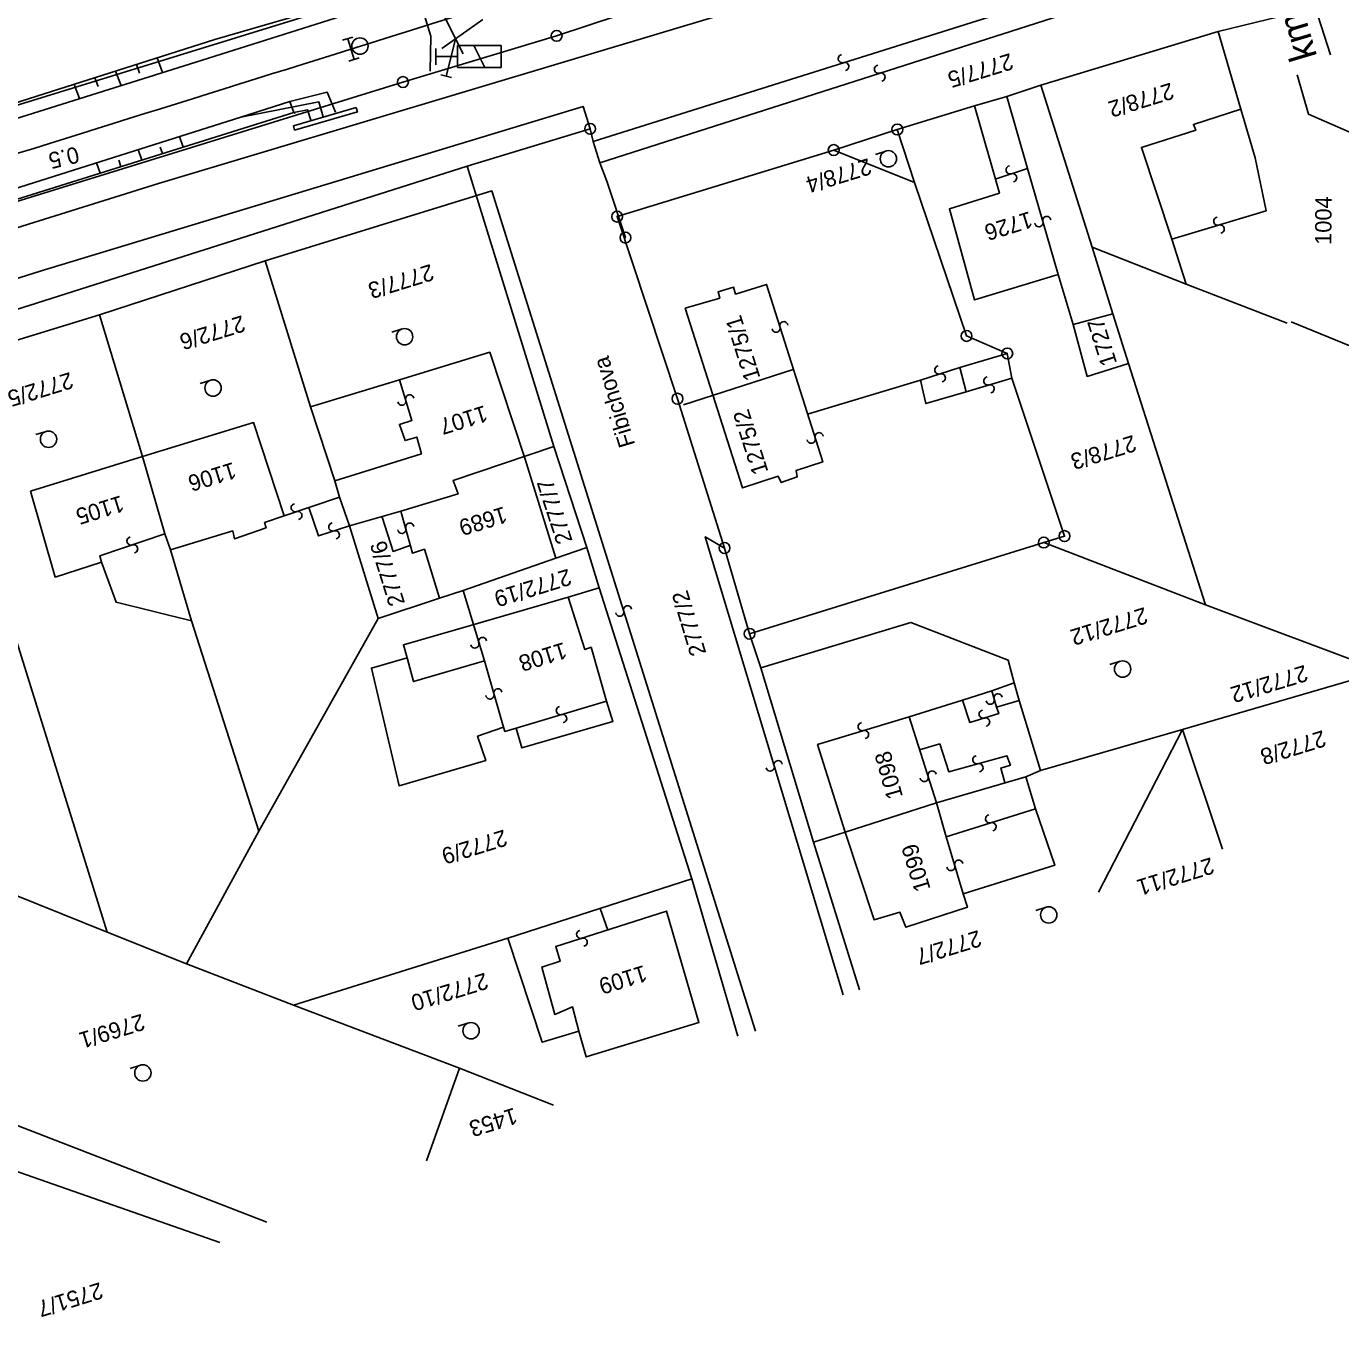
# Model space of a CAD drawing. Extents: x -658910 to -658078, y -1170373 to -1169331.
# Drawn here: x -658648.2 to -658527.6, y -1170123.2 to -1170003.8 of the extents above; entities that cross this region are included whole.
import ezdxf

# ---------------------------------------------------------------- set-up
doc = ezdxf.new("R2010")
doc.units = 0
for name, color, linetype in [('Vrstva 1', 7, 'Continuous'), ('Vrstva 10', 7, 'Continuous'), ('Vrstva 11', 7, 'Continuous'), ('Vrstva 13', 7, 'Continuous'), ('Vrstva 20', 7, 'Continuous'), ('Vrstva 23', 7, 'Continuous'), ('Vrstva 30', 7, 'Continuous'), ('Vrstva 6', 7, 'Continuous'), ('Vrstva 8', 7, 'Continuous'), ('Vrstva 9', 7, 'Continuous')]:
    doc.layers.add(name, color=color, linetype=linetype)

msp = doc.modelspace()

# ---------------------------------------------------------------- linework, layer by layer
at = {"layer": 'Vrstva 1'}
for p, q in [((-658599.613, -1170004.705), (-658599.513, -1170004.705)), ((-658613.714, -1170008.939), (-658613.614, -1170008.939))]:
    msp.add_line(p, q, dxfattribs=at)
for points in [[(-658750.043, -1170042.514), (-658671.512, -1170017.973), (-658613.207, -1169999.979)], [(-658585.293, -1169999.957), (-658599.563, -1170004.705), (-658613.664, -1170008.939), (-658714.84, -1170040.211), (-658749.914, -1170050.912)]]:
    msp.add_lwpolyline(points, dxfattribs=at)
for centre in [(-658599.563, -1170004.705), (-658613.664, -1170008.939)]:
    msp.add_circle(centre, 0.499, dxfattribs=at)
at = {"layer": 'Vrstva 10'}
for p, q in [((-658636.22, -1170006.729), (-658635.715, -1170008.066)), ((-658640.032, -1170007.941), (-658639.533, -1170009.262)), ((-658638.126, -1170007.335), (-658637.827, -1170008.128)), ((-658643.844, -1170009.153), (-658643.351, -1170010.459)), ((-658641.938, -1170008.547), (-658641.639, -1170009.339)), ((-658621.753, -1170010.1), (-658621.753, -1170010.1)), ((-658633.815, -1170014.909), (-658634.156, -1170013.926)), ((-658637.632, -1170016.104), (-658637.97, -1170015.132)), ((-658635.723, -1170015.506), (-658635.926, -1170014.923)), ((-658641.449, -1170017.299), (-658641.783, -1170016.338)), ((-658639.541, -1170016.702), (-658639.743, -1170016.118))]:
    msp.add_line(p, q, dxfattribs=at)
for points in [[(-658858.81, -1170075.77), (-658835.33, -1170068.814), (-658806.5, -1170059.46), (-658781.728, -1170051.951), (-658759.08, -1170044.56), (-658716.43, -1170031.76), (-658690.72, -1170023.742), (-658663.72, -1170015.47), (-658630.927, -1170005.047), (-658619.527, -1170001.735), (-658614.09, -1169999.864), (-658613.911, -1169996.427), (-658615.839, -1169976.036), (-658616.28, -1169953.162), (-658614.25, -1169933.651)], [(-658610.105, -1169934.508), (-658612.959, -1169952.166), (-658613.171, -1169975.75), (-658611.485, -1169997.195), (-658611.739, -1169999.997), (-658613.983, -1170001.632), (-658619.297, -1170002.886), (-658632.661, -1170007.108), (-658660.45, -1170015.82), (-658687.716, -1170024.188), (-658719.16, -1170034.07), (-658752.32, -1170044.29), (-658781.421, -1170053.208), (-658807.34, -1170061.38), (-658834.998, -1170069.996)], [(-658619.86, -1170011.71), (-658620.63, -1170009.86), (-658624.05, -1170010.73), (-658623.66, -1170011.73)], [(-658623.66, -1170011.73), (-658624.05, -1170010.73), (-658620.63, -1170009.86), (-658619.86, -1170011.71)], [(-658623.66, -1170011.73), (-658661.96, -1170023.72), (-658756.86, -1170053.2), (-658808.03, -1170068.81), (-658856.9, -1170084.05), (-658891.09, -1170098.33)], [(-658628.54, -1170012.15), (-658624.05, -1170010.73)], [(-658628.54, -1170012.15), (-658621.38, -1170010.76), (-658620.97, -1170012.14)], [(-658623.66, -1170011.73), (-658622.409, -1170011.477), (-658622.11, -1170012.44)], [(-658623.66, -1170011.73), (-658622.409, -1170011.477), (-658622.11, -1170012.44)], [(-658623.615, -1170011.792), (-658623.56, -1170011.788)], [(-658714.67, -1170038.92), (-658662.28, -1170022.82), (-658628.54, -1170012.15)]]:
    msp.add_lwpolyline(points, dxfattribs=at)
at = {"layer": 'Vrstva 13'}
msp.add_lwpolyline([(-658611.169, -1170007.954), (-658611.101, -1170004.744), (-658611.699, -1170002.836), (-658609.401, -1170001.323), (-658608.825, -1169993.398)], dxfattribs=at)
at = {"layer": 'Vrstva 20'}
for p, q in [((-658610.65, -1170005.85), (-658610.65, -1170007.35)), ((-658607.15, -1170005.6), (-658606.15, -1170007.6))]:
    msp.add_line(p, q, dxfattribs=at)
msp.add_lwpolyline([(-658610.65, -1170006.6), (-658608.65, -1170006.6), (-658608.65, -1170007.6), (-658604.65, -1170007.6), (-658604.65, -1170005.6), (-658608.65, -1170005.6), (-658608.65, -1170006.6)], dxfattribs=at)
at = {"layer": 'Vrstva 23'}
msp.add_line((-658535.91, -1169983.41), (-658528.549, -1170006.455), dxfattribs=at)
at = {"layer": 'Vrstva 30'}
for p, q in [((-658610.209, -1170002.229), (-658608.149, -1170006.353)), ((-658610.089, -1170005.867), (-658606.329, -1170003.201)), ((-658609.69, -1170008.39), (-658608.84, -1170004.995)), ((-658610.175, -1170008.269), (-658609.205, -1170008.511))]:
    msp.add_line(p, q, dxfattribs=at)
at = {"layer": 'Vrstva 6'}
for p, q in [((-658619.21, -1170005.11), (-658618.254, -1170004.818)), ((-658618.732, -1170004.964), (-658618.148, -1170006.876)), ((-658618.626, -1170007.022), (-658617.67, -1170006.73))]:
    msp.add_line(p, q, dxfattribs=at)
msp.add_lwpolyline([(-658617.95, -1170011.29), (-658617.839, -1170011.674), (-658623.6, -1170013.35), (-658623.713, -1170012.962)], close=True, dxfattribs=at)
msp.add_circle((-658617.611, -1170005.638), 0.75, dxfattribs=at)
for centre, radius, start, end in [((-655551.219, -1179788.762), 10252.407, 107.0611194, 107.4078056), ((-665545.791, -1147911.264), 23155.173, 287.1664083, 287.4078056)]:
    msp.add_arc(centre, radius, start, end, dxfattribs=at)
at = {"layer": 'Vrstva 8'}
for p, q in [((-658596.534, -1170013.23), (-658596.434, -1170013.23)), ((-658596.534, -1170013.23), (-658596.434, -1170013.23)), ((-658568.347, -1170013.295), (-658568.247, -1170013.295)), ((-658568.347, -1170013.295), (-658568.247, -1170013.295)), ((-658574.187, -1170015.18), (-658574.087, -1170015.18)), ((-658574.187, -1170015.18), (-658574.087, -1170015.18)), ((-658594.058, -1170021.287), (-658593.958, -1170021.287)), ((-658593.296, -1170023.209), (-658593.196, -1170023.209)), ((-658561.995, -1170032.236), (-658561.895, -1170032.236)), ((-658558.261, -1170033.842), (-658558.161, -1170033.842)), ((-658558.261, -1170033.842), (-658558.161, -1170033.842)), ((-658588.519, -1170037.996), (-658588.419, -1170037.996)), ((-658588.469, -1170037.996), (-658588.469, -1170037.996)), ((-658612.945, -1170051.436), (-658612.945, -1170051.436)), ((-658584.202, -1170051.688), (-658584.102, -1170051.688)), ((-658584.202, -1170051.688), (-658584.102, -1170051.688)), ((-658554.905, -1170051.188), (-658554.805, -1170051.188)), ((-658554.905, -1170051.188), (-658554.805, -1170051.188)), ((-658553.007, -1170050.594), (-658552.907, -1170050.594)), ((-658614.563, -1170052), (-658614.563, -1170052)), ((-658581.909, -1170059.557), (-658581.809, -1170059.557)), ((-658581.909, -1170059.557), (-658581.809, -1170059.557)), ((-658595.57, -1170084.762), (-658595.57, -1170084.762)), ((-658594.848, -1170086.736), (-658594.848, -1170086.736))]:
    msp.add_line(p, q, dxfattribs=at)
for points in [[(-658750.074, -1170053.912), (-658680.031, -1170031.988), (-658636.086, -1170018.248), (-658589.152, -1170004.176), (-658575.438, -1170000.053)], [(-658550.277, -1169999.916), (-658596.203, -1170014.398), (-658595.582, -1170016.34), (-658544.246, -1169999.895)], [(-658533.199, -1170002.92), (-658538.844, -1170004.318), (-658555.117, -1170009.242), (-658558.262, -1170010.266), (-658561.211, -1170011.133), (-658568.297, -1170013.295), (-658574.137, -1170015.18), (-658594.008, -1170021.287), (-658588.469, -1170037.996), (-658584.152, -1170051.688), (-658581.859, -1170059.557), (-658580.82, -1170062.693), (-658575.98, -1170078.678), (-658571.766, -1170092.223)], [(-658536.777, -1170011.42), (-658538.844, -1170004.318)], [(-658531.621, -1170008.283), (-658530.559, -1170011.891), (-658520.141, -1170016.441), (-658499.16, -1170024.449)], [(-658561.211, -1170011.133), (-658558.922, -1170019.131), (-658563.516, -1170020.586), (-658561.223, -1170028.934), (-658553.531, -1170026.605), (-658552.176, -1170031.176), (-658550.867, -1170035.945), (-658547.074, -1170034.758), (-658548.531, -1170030.191), (-658550.422, -1170024.084), (-658555.117, -1170009.242)], [(-658558.262, -1170010.266), (-658556.359, -1170016.871), (-658559.305, -1170017.84)], [(-658750.188, -1170058.359), (-658687.98, -1170039.244), (-658646.949, -1170026.285), (-658597.125, -1170011.18), (-658596.484, -1170013.23), (-658607.781, -1170016.664), (-658688.078, -1170042.182), (-658726.527, -1170053.572), (-658749.891, -1170060.961)], [(-658534.461, -1170020.768), (-658543.102, -1170023.367), (-658545.898, -1170014.932), (-658540.906, -1170013.365), (-658541.121, -1170012.82), (-658536.777, -1170011.42), (-658535.473, -1170015.891)], [(-658596.484, -1170013.23), (-658596.203, -1170014.398)], [(-658576.543, -1170039.404), (-658566.176, -1170036.285), (-658562.57, -1170035.143), (-658558.211, -1170033.842), (-658561.945, -1170032.236), (-658566.734, -1170018.16), (-658568.297, -1170013.295)], [(-658566.734, -1170018.16), (-658574.137, -1170015.18)], [(-658582.945, -1170096.482), (-658587.148, -1170082.047), (-658595.668, -1170055.334), (-658596.781, -1170051.652), (-658599.809, -1170042.387), (-658607.781, -1170016.664)], [(-658595.582, -1170016.34), (-658594.961, -1170018.031), (-658593.246, -1170023.209)], [(-658534.461, -1170020.768), (-658535.473, -1170015.891)], [(-658520.141, -1170016.441), (-658526.789, -1170033.129), (-658532.16, -1170030.949)], [(-658556.359, -1170016.871), (-658553.531, -1170026.605)], [(-658641.512, -1170030.291), (-658626.313, -1170025.328), (-658605.512, -1170018.924), (-658581.305, -1170096.014)], [(-658541.805, -1170027.486), (-658543.102, -1170023.367)], [(-658550.422, -1170024.084), (-658541.805, -1170027.486), (-658532.527, -1170031.072)], [(-658615.93, -1170058.158), (-658618.578, -1170049.668), (-658619.496, -1170047.02), (-658619.926, -1170045.531), (-658622.141, -1170038.736), (-658626.313, -1170025.328)], [(-658640.809, -1170086.922), (-658656.988, -1170035.021), (-658641.512, -1170030.291), (-658637.563, -1170043.293), (-658635.52, -1170050.398), (-658634.996, -1170051.859), (-658633.07, -1170058.375), (-658626.898, -1170077.652), (-658633.539, -1170089.834)], [(-658552.176, -1170031.176), (-658548.531, -1170030.191)], [(-658599.637, -1170052.623), (-658602.48, -1170043.461), (-658605.699, -1170033.73), (-658613.969, -1170036.246), (-658612.844, -1170039.979), (-658613.984, -1170040.346), (-658613.465, -1170041.83), (-658612.402, -1170041.514), (-658611.961, -1170043.051), (-658619.926, -1170045.531)], [(-658557.797, -1170036.104), (-658558.211, -1170033.842)], [(-658523.781, -1170063), (-658540.004, -1170056.895), (-658547.074, -1170034.758)], [(-658577.844, -1170035.322), (-658587.91, -1170038.539)], [(-658561.992, -1170037.352), (-658562.57, -1170035.143)], [(-658622.141, -1170038.736), (-658613.969, -1170036.246)], [(-658540.004, -1170056.895), (-658554.855, -1170051.188), (-658552.957, -1170050.594), (-658557.797, -1170036.104), (-658561.992, -1170037.352), (-658565.688, -1170038.436), (-658566.176, -1170036.285)], [(-658647.836, -1170046.486), (-658637.563, -1170043.293), (-658627.375, -1170040.178), (-658624.551, -1170048.723), (-658619.496, -1170047.02)], [(-658613.844, -1170048.316), (-658608.605, -1170046.717), (-658609.059, -1170045.496), (-658599.809, -1170042.387)], [(-658647.836, -1170046.486), (-658645.57, -1170054.359), (-658641.313, -1170052.986)], [(-658618.578, -1170049.668), (-658621.402, -1170050.576), (-658622.309, -1170047.979)], [(-658624.551, -1170048.723), (-658626.359, -1170049.342), (-658626.223, -1170049.822), (-658626.223, -1170049.822), (-658629.113, -1170050.855), (-658629.273, -1170050.123), (-658634.996, -1170051.859)], [(-658618.578, -1170049.668), (-658613.844, -1170048.316), (-658612.789, -1170052.17), (-658611.691, -1170051.805), (-658610.297, -1170056.289)], [(-658615.57, -1170048.859), (-658614.563, -1170052), (-658612.945, -1170051.436)], [(-658635.52, -1170050.398), (-658641.477, -1170052.41), (-658641.313, -1170052.986), (-658639.992, -1170056.662), (-658633.07, -1170058.375)], [(-658606.188, -1170062.025), (-658608.148, -1170055.572), (-658599.637, -1170052.623), (-658596.781, -1170051.652)], [(-658573.27, -1170092.689), (-658585.922, -1170050.66), (-658584.152, -1170051.688)], [(-658554.855, -1170051.188), (-658581.859, -1170059.557)], [(-658595.668, -1170055.334), (-658598.504, -1170056.197), (-658607.238, -1170058.742), (-658613.617, -1170060.563), (-658613.27, -1170061.762), (-658616.559, -1170062.701), (-658614.023, -1170073.51), (-658606.063, -1170071.186), (-658606.809, -1170068.957), (-658604.434, -1170068.123), (-658604.324, -1170068.508), (-658603.262, -1170068.203), (-658602.738, -1170070.027), (-658594.391, -1170067.594), (-658594.977, -1170065.734), (-658596.398, -1170060.791), (-658596.965, -1170061.004), (-658598.504, -1170056.197)], [(-658608.148, -1170055.572), (-658610.297, -1170056.289), (-658615.93, -1170058.158), (-658626.898, -1170077.652)], [(-658580.82, -1170062.693), (-658567.059, -1170058.518), (-658558.137, -1170061.963), (-658557.59, -1170064.049), (-658557.102, -1170065.688), (-658555.152, -1170072.094), (-658542.117, -1170068.344), (-658523.781, -1170063)], [(-658604.434, -1170068.123), (-658606.188, -1170062.025), (-658612.699, -1170063.936), (-658613.27, -1170061.762)], [(-658555.152, -1170072.094), (-658556.496, -1170072.674), (-658555.629, -1170075.604), (-658553.855, -1170080.793), (-658562.242, -1170083.406), (-658561.863, -1170084.648), (-658567.504, -1170086.479), (-658568.055, -1170085.096), (-658570.43, -1170085.797), (-658573.07, -1170077.756), (-658575.609, -1170069.715), (-658567.223, -1170067.172), (-658562.328, -1170065.658), (-658559.633, -1170064.797), (-658557.59, -1170064.049)], [(-658557.102, -1170065.688), (-658559.199, -1170066.287), (-658559.633, -1170064.797)], [(-658594.977, -1170065.734), (-658603.262, -1170068.203)], [(-658559.199, -1170066.287), (-658558.984, -1170066.881), (-658561.633, -1170067.693), (-658562.328, -1170065.658)], [(-658567.223, -1170067.172), (-658564.688, -1170075.063), (-658563.813, -1170078.193), (-658562.242, -1170083.406)], [(-658549.832, -1170083.271), (-658542.117, -1170068.344)], [(-658538.461, -1170079.309), (-658542.117, -1170068.344)], [(-658566.25, -1170070.199), (-658564.402, -1170069.656), (-658563.574, -1170072.215), (-658558.234, -1170070.75), (-658557.926, -1170071.607), (-658558.813, -1170071.877), (-658558.418, -1170073.215)], [(-658575.98, -1170078.678), (-658573.07, -1170077.756), (-658564.688, -1170075.063), (-658556.496, -1170072.674)], [(-658671.484, -1170074.795), (-658660.113, -1170079.238), (-658657.473, -1170080.25), (-658653.578, -1170081.787), (-658640.809, -1170086.922), (-658633.539, -1170089.834), (-658623.715, -1170093.627), (-658608.461, -1170099.402), (-658611.504, -1170107.906)], [(-658563.813, -1170078.193), (-658555.629, -1170075.604)], [(-658587.148, -1170082.047), (-658604.043, -1170087.492)], [(-658623.715, -1170093.627), (-658604.043, -1170087.492), (-658600.879, -1170097.031), (-658597.512, -1170096.018), (-658596.836, -1170098.369), (-658586.5, -1170095.211), (-658589.488, -1170085), (-658599.637, -1170088.26), (-658599.25, -1170089.604), (-658600.93, -1170090.135), (-658599.734, -1170094.469), (-658598.098, -1170093.795), (-658597.512, -1170096.018)], [(-658594.848, -1170086.736), (-658595.57, -1170084.762)], [(-658626.145, -1170113.541), (-658660.148, -1170100.391), (-658673.301, -1170095.209), (-658673.168, -1170095.848)], [(-658608.461, -1170099.402), (-658599.844, -1170102.813)], [(-658662.316, -1170128.127), (-658663.34, -1170124.938), (-658655.801, -1170122.422), (-658649.43, -1170108.76), (-658630.473, -1170115.4)]]:
    msp.add_lwpolyline(points, dxfattribs=at)
msp.add_lwpolyline([(-658587.754, -1170029.691), (-658584.598, -1170028.754), (-658584.742, -1170028.189), (-658583.34, -1170027.75), (-658583.145, -1170028.389), (-658580.289, -1170027.504), (-658575.141, -1170043.785), (-658577.594, -1170044.564), (-658577.488, -1170045.162), (-658578.941, -1170045.68), (-658579.246, -1170045.084), (-658582.504, -1170046.172)], close=True, dxfattribs=at)
for centre in [(-658596.484, -1170013.23), (-658596.484, -1170013.23), (-658568.297, -1170013.295), (-658568.297, -1170013.295), (-658574.137, -1170015.18), (-658574.137, -1170015.18), (-658594.008, -1170021.287), (-658593.246, -1170023.209), (-658561.945, -1170032.236), (-658558.211, -1170033.842), (-658558.211, -1170033.842), (-658588.469, -1170037.996), (-658552.957, -1170050.594), (-658584.152, -1170051.688), (-658584.152, -1170051.688), (-658554.855, -1170051.188), (-658554.855, -1170051.188), (-658581.859, -1170059.557), (-658581.859, -1170059.557)]:
    msp.add_circle(centre, 0.499, dxfattribs=at)
for centre, radius, start, end in [((-658573.351, -1170006.797), 0.376, 100.53272, 286.84385), ((-658573.128, -1170007.517), 0.377, 279.85667, 107.51989), ((-658570.024, -1170007.757), 0.376, 100.79306, 287.1042), ((-658569.799, -1170008.475), 0.377, 280.11702, 107.78024), ((-658557.945, -1170016.996), 0.376, 101.23704, 287.54817), ((-658557.714, -1170017.712), 0.377, 280.561, 108.22421), ((-658554.582, -1170021.637), 0.376, 9.23051, 195.54164), ((-658538.885, -1170021.706), 0.376, 99.77474, 286.08587), ((-658555.306, -1170021.843), 0.377, 188.55447, 16.21768), ((-658538.672, -1170022.428), 0.377, 279.0987, 106.76191), ((-658578.706, -1170031.299), 0.377, 9.72219, 197.38541), ((-658579.426, -1170031.52), 0.376, 190.39824, 16.70937), ((-658564.484, -1170035.354), 0.376, 100.61384, 286.92498), ((-658564.261, -1170036.074), 0.377, 279.9378, 107.60101), ((-658559.998, -1170036.365), 0.376, 99.59736, 285.9085), ((-658559.787, -1170037.088), 0.377, 278.92132, 106.58454), ((-658613.767, -1170038.215), 0.376, 189.80385, 16.11498), ((-658613.045, -1170038.002), 0.377, 9.12781, 196.79102), ((-658576.199, -1170041.706), 0.376, 190.78057, 17.09171), ((-658575.481, -1170041.481), 0.377, 10.10453, 197.76774), ((-658623.544, -1170047.991), 0.376, 101.39041, 287.70155), ((-658623.311, -1170048.707), 0.377, 280.71437, 108.37759), ((-658620.099, -1170049.761), 0.376, 100.85694, 287.16808), ((-658619.872, -1170050.479), 0.377, 280.1809, 107.84412), ((-658613.757, -1170049.975), 0.376, 189.09888, 15.41002), ((-658613.033, -1170049.77), 0.377, 8.42284, 196.08606), ((-658638.612, -1170051.046), 0.376, 101.69044, 288.00157), ((-658638.375, -1170051.76), 0.377, 281.01439, 108.67761), ((-658593.766, -1170057.577), 0.376, 190.46321, 16.77434), ((-658593.046, -1170057.356), 0.377, 9.78717, 197.45038), ((-658606.352, -1170060.27), 0.377, 10.10144, 197.76465), ((-658607.07, -1170060.495), 0.376, 190.77748, 17.08861), ((-658604.951, -1170064.969), 0.377, 8.40147, 196.06468), ((-658605.675, -1170065.173), 0.376, 189.07751, 15.38864), ((-658559.775, -1170065.648), 0.377, 188.57704, 16.24026), ((-658559.051, -1170065.442), 0.376, 9.25309, 195.56422), ((-658599.22, -1170066.607), 0.376, 99.62297, 285.93411), ((-658599.009, -1170067.329), 0.377, 278.94693, 106.61015), ((-658560.415, -1170066.925), 0.376, 100.08557, 286.3967), ((-658560.198, -1170067.647), 0.377, 279.40953, 107.07274), ((-658571.523, -1170068.081), 0.376, 99.89839, 286.20952), ((-658571.308, -1170068.803), 0.377, 279.22234, 106.88556), ((-658561.001, -1170071.117), 0.376, 98.37056, 284.68169), ((-658579.959, -1170071.778), 0.376, 189.78408, 16.09522), ((-658579.237, -1170071.565), 0.377, 9.10804, 196.77126), ((-658565.11, -1170072.515), 0.377, 10.16578, 197.82899), ((-658560.806, -1170071.845), 0.377, 277.69452, 105.35773), ((-658565.828, -1170072.742), 0.376, 190.84182, 17.15296), ((-658559.828, -1170076.537), 0.376, 100.59126, 286.90239), ((-658559.605, -1170077.257), 0.377, 279.91521, 107.57843), ((-658562.666, -1170080.69), 0.377, 9.11853, 196.78174), ((-658563.388, -1170080.903), 0.376, 189.79457, 16.1057), ((-658597.351, -1170087.138), 0.376, 100.67662, 286.98776), ((-658597.127, -1170087.856), 0.377, 280.00058, 107.66379)]:
    msp.add_arc(centre, radius, start, end, dxfattribs=at)
at = {"layer": 'Vrstva 9'}
for p, q in [((-658569.344, -1170015.268), (-658570.295, -1170015.575)), ((-658613.73, -1170031.59), (-658614.686, -1170031.881)), ((-658631.305, -1170036.291), (-658632.261, -1170036.583)), ((-658646.406, -1170040.992), (-658647.362, -1170041.284)), ((-658547.848, -1170062.08), (-658548.803, -1170062.376)), ((-658554.625, -1170084.631), (-658555.579, -1170084.928)), ((-658607.637, -1170095.256), (-658608.591, -1170095.553)), ((-658637.754, -1170099.129), (-658638.708, -1170099.426))]:
    msp.add_line(p, q, dxfattribs=at)
for centre in [(-658569.113, -1170015.981), (-658613.511, -1170032.307), (-658631.085, -1170037.008), (-658646.186, -1170041.709), (-658547.625, -1170062.796), (-658554.401, -1170085.347), (-658607.413, -1170095.971), (-658637.53, -1170099.844)]:
    msp.add_circle(centre, 0.75, dxfattribs=at)

# ---------------------------------------------------------------- texts
at = {"layer": 'Vrstva 11'}
msp.add_text('0.5', height=1.5, rotation=193.55134, dxfattribs=at).set_placement((-658643.593, -1170014.829))
at = {"layer": 'Vrstva 23'}
msp.add_text('km 1,017', height=2.5, rotation=106.61095, dxfattribs=at).set_placement((-658529.755, -1170006.584))
at = {"layer": 'Vrstva 9'}
for s, rotation, p in [('2777/5', 197.15141, (-658557.945, -1170006.268)), ('2778/2', 197.15141, (-658543.203, -1170008.977)), ('2778/4', 197.15141, (-658570.957, -1170015.906)), ('1004', 89.7363, (-658528.468, -1170023.884)), ('1726', 197.15141, (-658556.168, -1170020.783)), ('2777/3', 197.15141, (-658611.121, -1170025.617)), ('2772/6', 197.15141, (-658628.422, -1170030.318)), ('1275/1', 107.36788, (-658580.844, -1170036.072)), ('1727', 107.69664, (-658548.117, -1170034.719)), ('Fibichova', 106.7537, (-658592.344, -1170042.199)), ('2772/5', 197.15141, (-658644.211, -1170035.529)), ('1107', 197.15141, (-658606.18, -1170038.578)), ('1275/2', 107.67501, (-658580.113, -1170044.686)), ('2778/3', 197.15141, (-658546.656, -1170041.299)), ('1106', 197.15141, (-658629.246, -1170043.789)), ('1105', 197.15141, (-658639.543, -1170046.838)), ('2777/7', 108.09369, (-658598.078, -1170051.031)), ('1689', 197.15141, (-658604.395, -1170047.855)), ('2777/6', 107.32475, (-658613.457, -1170056.75)), ('2772/19', 197.15141, (-658598.492, -1170053.572)), ('2777/2', 106.7537, (-658585.813, -1170061.33)), ('2772/12', 197.15141, (-658545.613, -1170057.096)), ('1108', 197.15141, (-658598.902, -1170060.307)), ('2772/12', 196.86159, (-658530.912, -1170062.394)), ('2772/8', 197.15141, (-658529.25, -1170068.383)), ('1098', 105.6144, (-658567.766, -1170074.496)), ('2772/9', 197.15141, (-658604.383, -1170077.496)), ('1099', 106.76421, (-658565.227, -1170082.963)), ('2772/11', 197.15141, (-658539.516, -1170080.047)), ('2772/7', 197.15141, (-658560.863, -1170086.725)), ('1109', 197.15141, (-658591.551, -1170089.93)), ('2772/10', 197.15141, (-658606.125, -1170090.627)), ('2769/1', 197.15141, (-658637.641, -1170094.395)), ('1453', 197.15141, (-658603.449, -1170103.004)), ('2751/7', 197.15141, (-658641.473, -1170119.029))]:
    msp.add_text(s, height=1.5, rotation=rotation, dxfattribs=at).set_placement(p)

doc.saveas('drawing.dxf')
